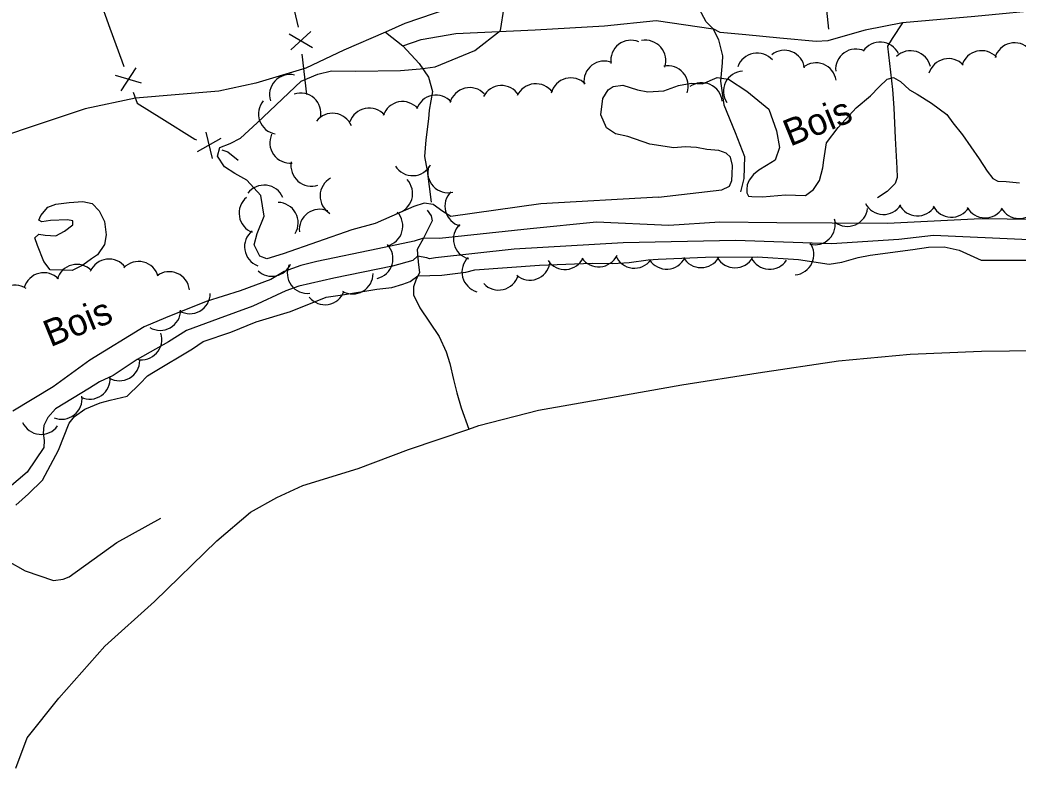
# Model space of a CAD drawing. Extents: x 362852 to 366875, y 5563573 to 5566479.
# Drawn here: x 364831.6 to 364978.4, y 5564751.1 to 5564861.3 of the extents above; entities that cross this region are included whole.
import ezdxf

# ---------------------------------------------------------------- set-up
doc = ezdxf.new("R2010")
doc.units = 0
for name, color, linetype in [('Niveau 2', 7, 'Continuous'), ('Niveau 22', 7, 'Continuous'), ('Niveau 37', 7, 'Continuous'), ('Niveau 4', 7, 'Continuous'), ('Niveau 44', 7, 'Continuous')]:
    doc.layers.add(name, color=color, linetype=linetype)

msp = doc.modelspace()

# ---------------------------------------------------------------- linework, layer by layer
at = {"layer": 'Niveau 2'}
for points in [[(364925.54, 5564835.16), (364908.2, 5564834.19), (364894.96, 5564832.31), (364893.78, 5564833.07), (364892.36, 5564834.1), (364891.04, 5564834.29), (364889.51, 5564833.79), (364883.83, 5564831.31), (364880.37, 5564830.38), (364870.3, 5564826.83), (364867.88, 5564826.07), (364866.83, 5564826.51), (364866.02, 5564828.16), (364866.45, 5564829.83), (364867.51, 5564832.38), (364867.01, 5564835.4), (364864.96, 5564837.66), (364863.18, 5564838.66), (364861.65, 5564839.65), (364860.64, 5564841.21), (364860.98, 5564842.47), (364862.47, 5564843.09), (364864.01, 5564843.85), (364866.44, 5564846.1), (364872.95, 5564852.27), (364875.38, 5564853.28), (364877.42, 5564853.75), (364880.91, 5564853.7), (364887.56, 5564853.84), (364890.45, 5564854.05), (364892.68, 5564854.35), (364898.51, 5564856.76), (364902.27, 5564859.68), (364902.82, 5564863.14)], [(364925.54, 5564835.16), (364934.86, 5564836.27), (364935.98, 5564836.8), (364936.34, 5564837.61), (364936.38, 5564838.56), (364936.42, 5564839.82), (364936.1, 5564841.05), (364935.47, 5564841.67), (364934.4, 5564842.03), (364932.66, 5564842.18), (364931.11, 5564842.47), (364929.45, 5564842.59), (364927.77, 5564842.45), (364924.26, 5564842.99), (364921, 5564844.12), (364919.18, 5564844.48), (364917.88, 5564845.37), (364917.02, 5564847.31), (364917.34, 5564849.68), (364918.1, 5564850.99), (364918.83, 5564851.48), (364920.26, 5564851.64), (364922.45, 5564850.99), (364923.94, 5564850.68), (364926.29, 5564850.84), (364928.45, 5564851.61), (364930.35, 5564851.97), (364932.02, 5564851.85), (364934.17, 5564852.8), (364935.82, 5564852.55), (364938.54, 5564850.76), (364941.74, 5564848.11), (364942.88, 5564844.92), (364943.32, 5564842.49), (364942.72, 5564840.63), (364941.43, 5564839.85), (364940.3, 5564839.13), (364939.49, 5564838.5), (364938.88, 5564837.66), (364938.57, 5564836.97), (364938.51, 5564836.29), (364938.53, 5564835.8), (364938.76, 5564835.31), (364939.24, 5564835.29), (364940.84, 5564835.24), (364944.24, 5564835.5), (364947.14, 5564835.41), (364948.35, 5564836.31), (364949.24, 5564837.61), (364949.71, 5564839.48), (364949.86, 5564840.61), (364950.23, 5564843.18), (364951.96, 5564845.45), (364954.61, 5564848.34), (364956.74, 5564850.09), (364957.99, 5564851.42), (364959.2, 5564852.54), (364960.09, 5564852.79), (364961.13, 5564852.22), (364962.45, 5564850.97), (364963.59, 5564850.32), (364965.68, 5564849.01), (364967.97, 5564847.36), (364968.86, 5564846.11), (364970.28, 5564844.34), (364972.72, 5564840.82), (364973.9, 5564839.01), (364974.72, 5564837.92), (364975.49, 5564837.55), (364976.7, 5564837.49), (364978.64, 5564837.3)], [(364842.08, 5564826.11), (364840.81, 5564825.15), (364839.21, 5564824.36), (364837.69, 5564824.42), (364836, 5564824.46), (364835.06, 5564825.69), (364834.15, 5564828.05), (364833.74, 5564829.18), (364834.32, 5564829.73), (364835.26, 5564829.56), (364836.85, 5564829.47), (364838.11, 5564830.18), (364839.33, 5564831.12), (364839.35, 5564831.69), (364838.54, 5564831.85), (364836.03, 5564831.75), (364834.76, 5564831.53), (364834.34, 5564831.79), (364834.62, 5564832.46), (364835.66, 5564833.7), (364836.85, 5564834.13), (364838.79, 5564834.38), (364840.78, 5564834.52), (364842.2, 5564834.24), (364843.21, 5564833.16), (364843.97, 5564831.61), (364844.24, 5564829.61), (364844.01, 5564828.21), (364842.97, 5564826.67), (364842.08, 5564826.11)], [(364984.59, 5564831.83), (364972.98, 5564831.99), (364959.23, 5564831.28), (364942.92, 5564831.37), (364934.54, 5564831.51), (364927.04, 5564831.01), (364916.42, 5564831.47), (364906.62, 5564830.52), (364893.29, 5564829.11), (364890.92, 5564829.13), (364889.55, 5564828.68), (364884.22, 5564827.59), (364875.25, 5564825.69), (364872.87, 5564825.13), (364870.44, 5564824.25), (364868.45, 5564823.06), (364863.98, 5564821.39), (364858.97, 5564819.82), (364852.95, 5564817.39), (364849.82, 5564816.09), (364841.85, 5564811.17), (364836.44, 5564807.26), (364830.52, 5564803.68)], [(364980.1, 5564828.88), (364966.02, 5564829.53), (364960.92, 5564828.92), (364950.98, 5564828.29), (364936.84, 5564828.79), (364920.31, 5564828.43), (364904.26, 5564827.51), (364892.72, 5564826.22), (364891.84, 5564826.11), (364891.41, 5564826.24), (364890.07, 5564826.49), (364889.39, 5564825.84), (364886.37, 5564825.03), (364877.76, 5564823.27), (364872.59, 5564822.07), (364870.69, 5564821.4), (364865.83, 5564819.14), (364860.7, 5564817.27), (364856.06, 5564815.53), (364853.39, 5564813.87), (364848.79, 5564811.28), (364845.29, 5564808.9), (364843.24, 5564807.99), (364841.76, 5564807.06), (364836.79, 5564804.01), (364835.64, 5564802.72), (364835.07, 5564801.55), (364834.96, 5564800.45), (364835.11, 5564799.33), (364835.04, 5564798.3), (364832.61, 5564794.68), (364828.96, 5564791.61)], [(364837.21, 5564797.94), (364838.81, 5564801.91), (364839.58, 5564802.91), (364841.08, 5564803.97), (364843.37, 5564804.92), (364844.84, 5564805.28), (364847.34, 5564805.87), (364849.2, 5564807.71), (364850.34, 5564808.87), (364851.18, 5564809.4), (364856.93, 5564812.84), (364858.53, 5564813.94), (364862.58, 5564815.31), (364866.33, 5564816.8), (364871.37, 5564818.32), (364876.61, 5564820.43), (364879.02, 5564820.8), (364884.09, 5564821.65), (364886.3, 5564821.88), (364887.91, 5564822.36), (364889, 5564822.74), (364890.13, 5564823.58), (364893.66, 5564823.68), (364897.15, 5564824.12), (364898.5, 5564824.49), (364908, 5564825.18), (364915.74, 5564825.45), (364918.81, 5564825.41), (364921.19, 5564825.53), (364924.01, 5564825.95), (364925.46, 5564826.05), (364932.45, 5564826.32), (364940.1, 5564826.37), (364946.11, 5564825.99), (364950.64, 5564825.3), (364952.51, 5564825.58), (364954.89, 5564826.31), (364956.69, 5564826.62), (364962.95, 5564827.47), (364965.25, 5564827.79), (364967.58, 5564827.88), (364969.78, 5564827.36), (364973.01, 5564825.89), (364981.42, 5564825.88)], [(364830.95, 5564789.85), (364832.82, 5564791.5), (364834.85, 5564793.53), (364837.21, 5564797.94)]]:
    msp.add_lwpolyline(points, dxfattribs=at)
at = {"layer": 'Niveau 22'}
for points in [[(365020.02, 5564865.79), (365014.94, 5564866.34), (365007.86, 5564865.87), (364995.41, 5564864.38), (364983.3, 5564862.86), (364972.1, 5564861.76), (364961.45, 5564860.83), (364955.92, 5564859.76), (364952.98, 5564858.92), (364950.44, 5564858.17), (364948.74, 5564858.09), (364943.36, 5564858.58), (364938.36, 5564859.06), (364934.59, 5564859.41), (364933.55, 5564859.97), (364932.52, 5564860.97), (364931.14, 5564863.62), (364929.76, 5564866.52), (364928.08, 5564869.91), (364924.21, 5564876.05), (364922.85, 5564879.14), (364921.92, 5564885.35), (364922.19, 5564887.26), (364924.48, 5564890.14)], [(364921.92, 5564885.35), (364920.9, 5564881.75), (364918.56, 5564877.49), (364915.62, 5564874.41), (364911.41, 5564869.87), (364906.94, 5564867.34), (364902.99, 5564866.08), (364896.7, 5564863.64), (364888.2, 5564860.73), (364885.33, 5564859.48), (364879.23, 5564856.81), (364873.61, 5564854.18), (364866.25, 5564851.93), (364860.8, 5564850.77), (364848.56, 5564849.72), (364841.14, 5564848.19), (364831.86, 5564845.06), (364821.27, 5564841.41), (364820.46, 5564841.14), (364809.21, 5564837.9), (364799.25, 5564836.01), (364795.21, 5564835.22)], [(364887.92, 5564857.45), (364890.58, 5564858.37), (364895.7, 5564859.26), (364907.35, 5564859.82), (364917.57, 5564860.4), (364925.19, 5564861.16), (364933.55, 5564859.97)], [(364961.45, 5564860.83), (364959.93, 5564858.52), (364959.24, 5564857.41), (364959.94, 5564851.02), (364960.17, 5564848.3), (364960.35, 5564843.88), (364960.61, 5564839.44), (364960.66, 5564838.09), (364960.37, 5564837.16), (364959.18, 5564835.99), (364957.75, 5564835.08)], [(364885.33, 5564859.48), (364887.92, 5564857.45), (364890.32, 5564854.86), (364891.7, 5564852.82), (364892.27, 5564850.72), (364891.77, 5564847.96), (364891.68, 5564846.68), (364891.28, 5564843.63), (364891.08, 5564841.17), (364891.47, 5564839.04), (364892.06, 5564834.44)], [(364933.55, 5564859.97), (364934.35, 5564858.32), (364934.96, 5564855.96), (364934.88, 5564854.94), (364934.63, 5564852.25), (364935.16, 5564848.78), (364936.79, 5564844.67), (364938.17, 5564841.18), (364938.06, 5564837.92), (364937.6, 5564835.95)], [(364813.64, 5564795.41), (364813.85, 5564794.47), (364814.41, 5564791.69), (364815.77, 5564789.07), (364819.11, 5564786.54), (364823.34, 5564784.36), (364827.07, 5564783.12), (364832.34, 5564780.15), (364836.48, 5564778.74), (364837.89, 5564778.95), (364838.79, 5564779.28), (364845.83, 5564784.32), (364852.27, 5564787.92)]]:
    msp.add_lwpolyline(points, dxfattribs=at)
at = {"layer": 'Niveau 37'}
for p, q in [((364872.54, 5564860.18), (364871.19, 5564866.03)), ((364950.6, 5564859.92), (364949.99, 5564865.89)), ((364842.74, 5564865.67), (364844.79, 5564860.03)), ((364871.15, 5564859.22), (364874.6, 5564857.19)), ((364871.42, 5564856.84), (364874.34, 5564859.58)), ((364873.76, 5564850.26), (364873.1, 5564856.22)), ((364848.61, 5564854.19), (364846.42, 5564850.84)), ((364849.43, 5564851.93), (364845.6, 5564853.1)), ((364858.9, 5564844.76), (364859.82, 5564840.86)), ((364861.1, 5564843.79), (364857.62, 5564841.82))]:
    msp.add_line(p, q, dxfattribs=at)
for points in [[(364844.79, 5564860.03), (364846.53, 5564855.24), (364846.84, 5564854.39)], [(364848.2, 5564850.63), (364848.78, 5564849.03), (364852.43, 5564846.76)], [(364852.43, 5564846.76), (364857.31, 5564843.71), (364857.53, 5564843.61)], [(364861.24, 5564842.13), (364862.12, 5564841.85), (364863.66, 5564840.6)]]:
    msp.add_lwpolyline(points, dxfattribs=at)
at = {"layer": 'Niveau 4'}
for points in [[(364891.48, 5564833.24), (364892.07, 5564832.43), (364892.23, 5564831.71), (364890.92, 5564829.13), (364890, 5564827.47), (364890.14, 5564825.65), (364890.35, 5564824.01), (364889.87, 5564823.09), (364889.47, 5564821.96), (364889.45, 5564820.79), (364890.4, 5564818.86), (364893.23, 5564814.64), (364894.26, 5564812.41), (364894.8, 5564810.7), (364895.36, 5564808.35), (364895.85, 5564806.39), (364896.48, 5564804.15), (364897.59, 5564801.03)], [(364830.95, 5564751.14), (364832.62, 5564755.58), (364837.26, 5564761.44), (364844.04, 5564769.06), (364851.37, 5564775.66), (364860.5, 5564784.57), (364865.48, 5564788.82), (364869.34, 5564790.98), (364873.17, 5564792.75), (364881.31, 5564795.25), (364888.73, 5564798.01), (364897.59, 5564801.03), (364899.07, 5564801.54), (364907.87, 5564803.81), (364918.46, 5564805.69), (364928.94, 5564807.53), (364940.19, 5564809.31), (364952, 5564811.08), (364962.57, 5564812.08), (364973.07, 5564812.49), (364985.37, 5564812.64)]]:
    msp.add_lwpolyline(points, dxfattribs=at)
at = {"layer": 'Niveau 44'}
for centre, start, end in [((364921.49, 5564855.27), 67.6861, 187.664), ((364923.6, 5564855.27), 341.1357, 101.1137), ((364958.14, 5564855), 25.9502, 145.9282), ((364977.93, 5564854.89), 43.4788, 163.4567), ((364940.05, 5564853.39), 41.0985, 161.0764), ((364944.05, 5564853.79), 8.3351, 128.313), ((364954.59, 5564853.97), 65.2331, 185.211), ((364962.63, 5564853.72), 13.4676, 133.4455), ((364973.07, 5564853.73), 43.4788, 163.4567), ((364917.54, 5564852.21), 67.6861, 187.664), ((364926.89, 5564851.5), 341.1357, 101.1137), ((364948.7, 5564851.94), 8.3351, 128.313), ((364968.21, 5564852.56), 43.4788, 163.4567), ((364871.27, 5564850.22), 77.1622, 197.1402), ((364912.64, 5564849.73), 45.1984, 165.1764), ((364938.08, 5564850.73), 93.2977, 213.2757), ((364897.73, 5564848.29), 44.1021, 164.08), ((364902.42, 5564848.6), 32.9364, 152.9143), ((364907.47, 5564848.87), 35.3486, 155.3266), ((364931.92, 5564849.01), 5.9858, 125.9637), ((364872.85, 5564847.5), 348.0489, 108.0269), ((364892.77, 5564847.19), 41.0755, 161.0535), ((364869.65, 5564847.43), 139.72, 259.6979), ((364882.95, 5564845.28), 41.0755, 161.0535), ((364887.86, 5564846.24), 41.0755, 161.0535), ((364877.55, 5564844.52), 22.4719, 142.4499), ((364871.32, 5564843.18), 155.3198, 275.2978), ((364874.43, 5564839.79), 169.0541, 289.032), ((364889.34, 5564841.34), 212.2429, 332.2209), ((364894.57, 5564838.83), 163.32, 283.2979), ((364878.72, 5564835.34), 118.8756, 238.8535), ((364867.48, 5564833.94), 23.0135, 142.9914), ((364886.34, 5564835.71), 283.1848, 43.1627), ((364866.8, 5564832.81), 129.2675, 249.2454), ((364897.09, 5564833.84), 134.547, 254.5249), ((364869.49, 5564831.4), 328.7549, 88.7329), ((364958.64, 5564835.63), 207.6652, 327.6432), ((364963.63, 5564835.42), 207.6652, 327.6432), ((364968.63, 5564835.22), 207.6652, 327.6432), ((364973.59, 5564835.12), 209.0163, 328.9942), ((364978.59, 5564835.03), 209.0163, 328.9942), ((364875.66, 5564830.39), 66.5277, 186.5056), ((364884.9, 5564830.92), 283.1848, 43.1627), ((364953.33, 5564833.87), 232.9458, 352.9237), ((364898.35, 5564829), 134.547, 254.5249), ((364948.53, 5564831.16), 255.4277, 15.4056), ((364867.6, 5564827.88), 129.2675, 249.2454), ((364883.45, 5564826.13), 283.1848, 43.1627), ((364945.39, 5564826.72), 275.1953, 35.1732), ((364899.6, 5564824.15), 134.3892, 254.3671), ((364911.74, 5564827.53), 214.42, 334.398), ((364916.73, 5564827.91), 214.42, 334.398), ((364921.99, 5564827.72), 203.4632, 323.4412), ((364926.71, 5564827.58), 213.4043, 333.3823), ((364931.79, 5564827.8), 209.8742, 329.8522), ((364936.79, 5564827.78), 209.8742, 329.8522), ((364941.88, 5564827.55), 206.3924, 326.3703), ((364839.92, 5564822.27), 44.1411, 164.119), ((364844.65, 5564823.06), 36.6317, 156.6097), ((364849.02, 5564822.7), 16.0637, 136.0416), ((364868.63, 5564826.53), 227.4442, 335.7336), ((364873.89, 5564824), 156.3785, 276.3565), ((364906.6, 5564825.96), 229.5399, 349.5178), ((364835.07, 5564821.05), 44.1411, 164.119), ((364853.52, 5564821.2), 6.6522, 126.6302), ((364880.51, 5564823.92), 240.3407, 0.3186), ((364902, 5564824.5), 223.2543, 343.2322), ((364830.8, 5564819.22), 56.5353, 176.5133), ((364856.56, 5564821.02), 239.4144, 359.3924), ((364876.43, 5564822.34), 219.4306, 339.4085), ((364852.2, 5564818.56), 239.4144, 359.3924), ((364849.44, 5564814.24), 257.5756, 17.5535), ((364846.18, 5564811.14), 239.9597, 359.9376), ((364841.82, 5564808.44), 244.9142, 4.8922), ((364837.7, 5564805.49), 247.7307, 7.7086), ((364834.67, 5564803.25), 204.0782, 324.0561)]:
    msp.add_arc(centre, 3, start, end, dxfattribs=at)

# ---------------------------------------------------------------- texts
for p in [(364944.9, 5564842.59), (364836.03, 5564813.07)]:
    msp.add_text('Bois', height=3.93, rotation=22.09, dxfattribs=at).set_placement(p)

doc.saveas('drawing.dxf')
